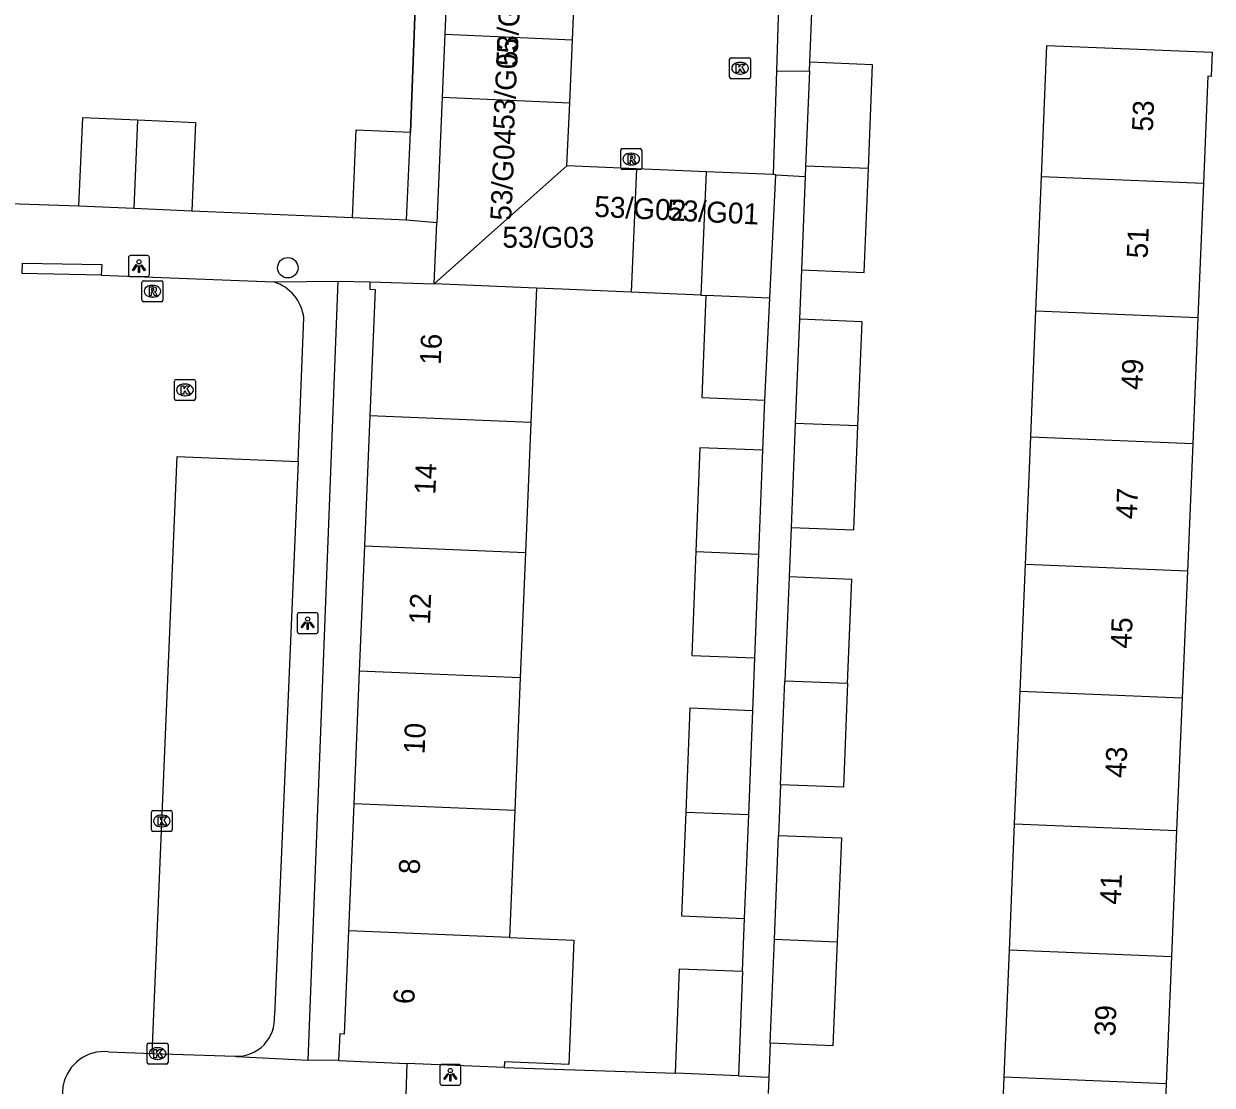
# Model space of a CAD drawing. Extents: x 161355 to 162026, y 386504 to 387459.
# Drawn here: x 161688.1 to 161744.9, y 387342.4 to 387393.1 of the extents above; entities that cross this region are included whole.
import ezdxf

# ---------------------------------------------------------------- set-up
doc = ezdxf.new("R2010")
doc.units = 0
for name, color, linetype in [('IMGEO_Boom', 7, 'Continuous'), ('IMGEO_Kolk', 7, 'Continuous'), ('IMGEO_Lichtpunt', 7, 'Continuous'), ('IMGEO_Muur', 7, 'Continuous'), ('IMGEO_Pand', 7, 'Continuous'), ('IMGEO_Pand_nummerreeks', 7, 'Continuous'), ('IMGEO_Rijbaan_lokaal_open', 7, 'Continuous'), ('IMGEO_Rioolput', 7, 'Continuous'), ('IMGEO_Voetpad_open', 7, 'Continuous')]:
    doc.layers.add(name, color=color, linetype=linetype)

msp = doc.modelspace()

# ---------------------------------------------------------------- linework, layer by layer
at = {"layer": 'IMGEO_Boom'}
msp.add_circle((161700.747, 387381.482), 0.489, dxfattribs=at)
at = {"layer": 'IMGEO_Kolk'}
for p, q in [((161721.849, 387390.588), (161721.849, 387391.44)), ((161721.924, 387391.514), (161722.776, 387391.514)), ((161722.337, 387391.294), (161722.362, 387391.294)), ((161722.85, 387391.44), (161722.85, 387390.588)), ((161722.776, 387390.514), (161721.924, 387390.514)), ((161722.36, 387390.734), (161722.335, 387390.734)), ((161695.335, 387375.22), (161695.335, 387376.072)), ((161695.41, 387376.146), (161696.262, 387376.146)), ((161695.823, 387375.926), (161695.848, 387375.926)), ((161696.336, 387376.072), (161696.336, 387375.22)), ((161696.262, 387375.146), (161695.41, 387375.146)), ((161695.846, 387375.366), (161695.821, 387375.366)), ((161694.231, 387354.628), (161694.231, 387355.48)), ((161694.306, 387355.554), (161695.158, 387355.554)), ((161694.719, 387355.334), (161694.744, 387355.334)), ((161695.232, 387355.48), (161695.232, 387354.628)), ((161694.742, 387354.774), (161694.717, 387354.774)), ((161695.158, 387354.554), (161694.306, 387354.554)), ((161694.029, 387343.517), (161694.029, 387344.369)), ((161694.104, 387344.443), (161694.956, 387344.443)), ((161694.517, 387344.223), (161694.542, 387344.223)), ((161695.03, 387344.369), (161695.03, 387343.517)), ((161694.956, 387343.443), (161694.104, 387343.443)), ((161694.54, 387343.663), (161694.515, 387343.663))]:
    msp.add_line(p, q, dxfattribs=at)
for points in [[(161721.849, 387390.588), (161721.849, 387391.44)], [(161721.924, 387391.514), (161722.776, 387391.514)], [(161722.17, 387391.214), (161722.293, 387391.214), (161722.293, 387391.063), (161722.423, 387391.214), (161722.587, 387391.214), (161722.441, 387391.063), (161722.594, 387390.814), (161722.442, 387390.814), (161722.357, 387390.978), (161722.293, 387390.911), (161722.293, 387390.814), (161722.17, 387390.814), (161722.17, 387391.214)], [(161722.85, 387391.44), (161722.85, 387390.588)], [(161722.776, 387390.514), (161721.924, 387390.514)], [(161695.335, 387375.22), (161695.335, 387376.072)], [(161695.41, 387376.146), (161696.262, 387376.146)], [(161695.656, 387375.846), (161695.779, 387375.846), (161695.779, 387375.695), (161695.909, 387375.846), (161696.073, 387375.846), (161695.927, 387375.695), (161696.08, 387375.446), (161695.928, 387375.446), (161695.843, 387375.61), (161695.779, 387375.543), (161695.779, 387375.446), (161695.656, 387375.446), (161695.656, 387375.846)], [(161696.336, 387376.072), (161696.336, 387375.22)], [(161696.262, 387375.146), (161695.41, 387375.146)], [(161694.231, 387354.628), (161694.231, 387355.48)], [(161694.306, 387355.554), (161695.158, 387355.554)], [(161695.232, 387355.48), (161695.232, 387354.628)], [(161694.552, 387355.254), (161694.675, 387355.254), (161694.675, 387355.103), (161694.805, 387355.254), (161694.969, 387355.254), (161694.823, 387355.103), (161694.976, 387354.854), (161694.824, 387354.854), (161694.739, 387355.018), (161694.675, 387354.951), (161694.675, 387354.854), (161694.552, 387354.854), (161694.552, 387355.254)], [(161695.158, 387354.554), (161694.306, 387354.554)], [(161694.029, 387343.517), (161694.029, 387344.369)], [(161694.104, 387344.443), (161694.956, 387344.443)], [(161694.35, 387344.143), (161694.473, 387344.143), (161694.473, 387343.992), (161694.603, 387344.143), (161694.767, 387344.143), (161694.621, 387343.992), (161694.774, 387343.743), (161694.622, 387343.743), (161694.537, 387343.907), (161694.473, 387343.84), (161694.473, 387343.743), (161694.35, 387343.743), (161694.35, 387344.143)], [(161695.03, 387344.369), (161695.03, 387343.517)], [(161694.956, 387343.443), (161694.104, 387343.443)]]:
    msp.add_lwpolyline(points, dxfattribs=at)
for centre, start, end in [((161721.926, 387391.438), 91.552, 178.448), ((161721.926, 387391.438), 91.552, 178.448), ((161722.774, 387391.438), 1.552, 88.448), ((161722.774, 387391.438), 1.552, 88.448), ((161721.926, 387390.59), 181.552, 268.448), ((161721.926, 387390.59), 181.552, 268.448), ((161722.774, 387390.59), 271.552, 358.448), ((161722.774, 387390.59), 271.552, 358.448), ((161695.412, 387376.07), 91.552, 178.448), ((161695.412, 387376.07), 91.552, 178.448), ((161696.26, 387376.07), 1.552, 88.448), ((161696.26, 387376.07), 1.552, 88.448), ((161695.412, 387375.222), 181.552, 268.448), ((161695.412, 387375.222), 181.552, 268.448), ((161696.26, 387375.222), 271.552, 358.448), ((161696.26, 387375.222), 271.552, 358.448), ((161694.308, 387355.478), 91.552, 178.448), ((161694.308, 387355.478), 91.552, 178.448), ((161695.156, 387355.478), 1.552, 88.448), ((161695.156, 387355.478), 1.552, 88.448), ((161694.308, 387354.63), 181.552, 268.448), ((161694.308, 387354.63), 181.552, 268.448), ((161695.156, 387354.63), 271.552, 358.448), ((161695.156, 387354.63), 271.552, 358.448), ((161694.106, 387344.367), 91.552, 178.448), ((161694.106, 387344.367), 91.552, 178.448), ((161694.954, 387344.367), 1.552, 88.448), ((161694.954, 387344.367), 1.552, 88.448), ((161694.106, 387343.519), 181.552, 268.448), ((161694.106, 387343.519), 181.552, 268.448), ((161694.954, 387343.519), 271.552, 358.448), ((161694.954, 387343.519), 271.552, 358.448)]:
    msp.add_arc(centre, 0.0765, start, end, dxfattribs=at)
for centre, major_axis, ratio, start_param, end_param in [((161722.336, 387391.014), (-0.387, 0.002), 0.722429, 4.712389, 7.853982), ((161722.361, 387391.014), (-0.39, 0.002), 0.717154, 1.570796, 4.712389), ((161695.822, 387375.646), (-0.387, 0.002), 0.722429, 4.712389, 7.853982), ((161695.847, 387375.646), (-0.39, 0.002), 0.717154, 1.570796, 4.712389), ((161694.718, 387355.054), (-0.387, 0.002), 0.722429, 4.712389, 7.853982), ((161694.743, 387355.054), (-0.39, 0.002), 0.717154, 1.570796, 4.712389), ((161694.516, 387343.943), (-0.387, 0.002), 0.722429, 4.712389, 7.853982), ((161694.541, 387343.943), (-0.39, 0.002), 0.717154, 1.570796, 4.712389)]:
    msp.add_ellipse(centre, major_axis=major_axis, ratio=ratio, start_param=start_param, end_param=end_param, dxfattribs=at)
at = {"layer": 'IMGEO_Lichtpunt'}
for p, q in [((161693.139, 387381.966), (161693.139, 387381.159)), ((161693.139, 387381.966), (161693.139, 387381.159)), ((161694.041, 387382.061), (161693.233, 387382.061)), ((161694.041, 387382.061), (161693.233, 387382.061)), ((161694.135, 387381.159), (161694.135, 387381.966)), ((161694.135, 387381.159), (161694.135, 387381.966)), ((161693.233, 387381.065), (161694.041, 387381.065)), ((161693.233, 387381.065), (161694.041, 387381.065)), ((161702.099, 387365.003), (161701.291, 387365.003)), ((161702.099, 387365.003), (161701.291, 387365.003)), ((161701.197, 387364.908), (161701.197, 387364.101)), ((161701.197, 387364.908), (161701.197, 387364.101)), ((161702.193, 387364.101), (161702.193, 387364.908)), ((161702.193, 387364.101), (161702.193, 387364.908)), ((161701.291, 387364.007), (161702.099, 387364.007)), ((161701.291, 387364.007), (161702.099, 387364.007)), ((161708.917, 387343.428), (161708.109, 387343.428)), ((161708.917, 387343.428), (161708.109, 387343.428)), ((161708.015, 387343.333), (161708.015, 387342.526)), ((161708.015, 387343.333), (161708.015, 387342.526)), ((161709.011, 387342.526), (161709.011, 387343.333)), ((161709.011, 387342.526), (161709.011, 387343.333)), ((161708.109, 387342.432), (161708.917, 387342.432)), ((161708.109, 387342.432), (161708.917, 387342.432))]:
    msp.add_line(p, q, dxfattribs=at)
for points in [[(161693.513, 387381.63), (161693.552, 387381.602), (161693.364, 387381.34), (161693.326, 387381.367), (161693.513, 387381.63)], [(161693.615, 387381.582), (161693.662, 387381.582), (161693.662, 387381.26), (161693.615, 387381.26), (161693.615, 387381.582)], [(161693.725, 387381.602), (161693.763, 387381.629), (161693.95, 387381.367), (161693.911, 387381.339), (161693.725, 387381.602)], [(161701.571, 387364.572), (161701.61, 387364.544), (161701.422, 387364.282), (161701.384, 387364.309), (161701.571, 387364.572)], [(161701.673, 387364.524), (161701.72, 387364.524), (161701.72, 387364.202), (161701.673, 387364.202), (161701.673, 387364.524)], [(161701.783, 387364.544), (161701.821, 387364.571), (161702.008, 387364.309), (161701.969, 387364.281), (161701.783, 387364.544)], [(161708.389, 387342.997), (161708.428, 387342.969), (161708.24, 387342.707), (161708.202, 387342.734), (161708.389, 387342.997)], [(161708.491, 387342.949), (161708.538, 387342.949), (161708.538, 387342.627), (161708.491, 387342.627), (161708.491, 387342.949)], [(161708.601, 387342.969), (161708.639, 387342.996), (161708.826, 387342.734), (161708.787, 387342.706), (161708.601, 387342.969)]]:
    msp.add_lwpolyline(points, dxfattribs=at)
for centre in [(161693.638, 387381.764), (161701.696, 387364.706), (161708.514, 387343.131)]:
    msp.add_circle(centre, 0.0994, dxfattribs=at)
for centre, start, end in [((161693.233, 387381.966), 90, 180), ((161693.233, 387381.966), 90, 180), ((161694.041, 387381.966), 0, 90), ((161694.041, 387381.966), 0, 90), ((161693.233, 387381.159), 180, 270), ((161693.233, 387381.159), 180, 270), ((161694.041, 387381.159), 270, 0), ((161694.041, 387381.159), 270, 360), ((161701.291, 387364.908), 90, 180), ((161701.291, 387364.908), 90, 180), ((161702.099, 387364.908), 0, 90), ((161702.099, 387364.908), 0, 90), ((161701.291, 387364.101), 180, 270), ((161701.291, 387364.101), 180, 270), ((161702.099, 387364.101), 270, 0), ((161702.099, 387364.101), 270, 360), ((161708.109, 387343.333), 90, 180), ((161708.109, 387343.333), 90, 180), ((161708.917, 387343.333), 0, 90), ((161708.917, 387343.333), 0, 90), ((161708.109, 387342.526), 180, 270), ((161708.109, 387342.526), 180, 270), ((161708.917, 387342.526), 270, 0), ((161708.917, 387342.526), 270, 360)]:
    msp.add_arc(centre, 0.0946, start, end, dxfattribs=at)
at = {"layer": 'IMGEO_Muur'}
msp.add_lwpolyline([(161706.839, 387393.897), (161706.606, 387387.966)], dxfattribs=at)
at = {"layer": 'IMGEO_Pand'}
for points in [[(161708.375, 387395.648), (161708.247, 387392.637)], [(161714.341, 387392.376), (161714.469, 387395.388)], [(161708.247, 387392.637), (161708.118, 387389.626)], [(161708.247, 387392.637), (161714.341, 387392.376)], [(161714.212, 387389.365), (161714.341, 387392.376)], [(161736.748, 387385.822), (161737.009, 387392.105), (161744.902, 387391.778), (161744.854, 387390.625), (161744.698, 387390.632), (161744.485, 387385.5)], [(161725.663, 387390.867), (161725.68, 387391.296)], [(161728.478, 387386.219), (161728.678, 387391.175), (161725.68, 387391.296)], [(161725.663, 387390.867), (161725.48, 387386.34)], [(161708.118, 387389.626), (161707.989, 387386.615), (161707.862, 387383.636)], [(161708.118, 387389.626), (161714.212, 387389.365)], [(161714.083, 387386.354), (161714.212, 387389.365)], [(161690.767, 387384.424), (161690.951, 387388.662), (161693.568, 387388.548)], [(161693.568, 387388.548), (161693.397, 387384.31)], [(161693.568, 387388.548), (161696.343, 387388.428), (161696.159, 387384.19)], [(161703.836, 387383.863), (161704.017, 387388.076), (161706.606, 387387.966)], [(161706.425, 387383.752), (161706.606, 387387.966)], [(161714.083, 387386.354), (161712.21, 387384.69), (161707.737, 387380.716)], [(161717.407, 387386.212), (161714.083, 387386.354)], [(161717.407, 387386.212), (161717.154, 387380.313)], [(161720.731, 387386.069), (161717.407, 387386.212)], [(161720.731, 387386.069), (161720.478, 387380.171)], [(161723.931, 387385.932), (161720.731, 387386.069)], [(161724.055, 387385.927), (161723.931, 387385.932)], [(161725.28, 387381.384), (161728.278, 387381.263), (161728.478, 387386.219)], [(161725.48, 387386.34), (161725.46, 387385.841)], [(161728.478, 387386.219), (161725.48, 387386.34)], [(161723.771, 387380.034), (161724.055, 387385.927)], [(161725.46, 387385.841), (161725.28, 387381.384)], [(161736.482, 387379.425), (161736.748, 387385.822)], [(161744.485, 387385.5), (161736.748, 387385.822)], [(161744.485, 387385.5), (161744.219, 387379.103)], [(161693.397, 387384.31), (161690.767, 387384.424)], [(161696.159, 387384.19), (161693.397, 387384.31)], [(161706.425, 387383.752), (161703.836, 387383.863)], [(161707.737, 387380.716), (161707.862, 387383.636)], [(161704.673, 387380.804), (161704.659, 387380.46), (161704.919, 387380.449), (161704.669, 387374.41)], [(161704.673, 387380.804), (161707.737, 387380.716)], [(161712.624, 387380.507), (161707.737, 387380.716)], [(161712.624, 387380.507), (161712.359, 387374.091)], [(161717.154, 387380.313), (161713.831, 387380.455), (161712.624, 387380.507)], [(161720.478, 387380.171), (161717.154, 387380.313)], [(161720.478, 387380.171), (161720.719, 387380.161)], [(161720.719, 387380.161), (161720.528, 387375.28), (161723.536, 387375.162)], [(161723.771, 387380.034), (161720.719, 387380.161)], [(161723.536, 387375.162), (161723.771, 387380.034)], [(161736.232, 387373.404), (161736.482, 387379.425)], [(161736.482, 387379.425), (161744.219, 387379.103)], [(161725.185, 387379.02), (161724.984, 387374.045)], [(161727.981, 387373.924), (161728.182, 387378.899), (161725.185, 387379.02)], [(161744.219, 387379.103), (161743.969, 387373.082)], [(161704.669, 387374.41), (161704.412, 387368.205)], [(161712.359, 387374.091), (161704.669, 387374.41)], [(161712.359, 387374.091), (161712.102, 387367.886)], [(161724.984, 387374.045), (161724.783, 387369.079)], [(161727.981, 387373.924), (161724.984, 387374.045)], [(161724.783, 387369.079), (161727.781, 387368.958), (161727.981, 387373.924)], [(161723.442, 387372.763), (161720.434, 387372.881), (161720.24, 387367.925)], [(161735.979, 387367.31), (161736.232, 387373.404)], [(161736.232, 387373.404), (161743.969, 387373.082)], [(161743.969, 387373.082), (161743.716, 387366.988)], [(161723.248, 387367.807), (161723.442, 387372.763)], [(161704.412, 387368.205), (161704.164, 387362.214)], [(161704.412, 387368.205), (161712.102, 387367.886)], [(161712.102, 387367.886), (161711.854, 387361.895)], [(161720.24, 387367.925), (161720.046, 387362.962), (161723.054, 387362.845)], [(161720.24, 387367.925), (161723.248, 387367.807)], [(161723.054, 387362.845), (161723.248, 387367.807)], [(161735.728, 387361.261), (161735.979, 387367.31)], [(161743.716, 387366.988), (161735.979, 387367.31)], [(161724.688, 387366.713), (161724.487, 387361.751)], [(161727.485, 387361.63), (161727.685, 387366.592), (161724.688, 387366.713)], [(161743.716, 387366.988), (161743.465, 387360.939)], [(161704.164, 387362.214), (161703.902, 387355.879)], [(161711.854, 387361.895), (161704.164, 387362.214)], [(161711.854, 387361.895), (161711.592, 387355.56)], [(161724.287, 387356.786), (161724.487, 387361.751)], [(161727.485, 387361.63), (161727.284, 387356.664), (161724.287, 387356.786)], [(161724.487, 387361.751), (161727.485, 387361.63)], [(161735.465, 387354.918), (161735.728, 387361.261)], [(161735.728, 387361.261), (161743.465, 387360.939)], [(161722.955, 387360.321), (161719.947, 387360.438), (161719.754, 387355.482)], [(161743.465, 387360.939), (161743.201, 387354.596)], [(161722.761, 387355.365), (161722.955, 387360.321)], [(161703.902, 387355.879), (161703.65, 387349.806)], [(161711.592, 387355.56), (161703.902, 387355.879)], [(161711.592, 387355.56), (161711.341, 387349.487)], [(161719.754, 387355.482), (161719.559, 387350.521), (161722.567, 387350.403)], [(161719.754, 387355.482), (161722.761, 387355.365)], [(161722.567, 387350.403), (161722.761, 387355.365)], [(161735.214, 387348.884), (161735.465, 387354.918)], [(161735.465, 387354.918), (161743.201, 387354.596)], [(161723.989, 387349.406), (161724.189, 387354.367)], [(161724.189, 387354.367), (161727.187, 387354.246), (161726.986, 387349.285)], [(161743.201, 387354.596), (161742.951, 387348.562)], [(161703.65, 387349.806), (161703.446, 387344.875), (161703.229, 387344.884), (161703.176, 387343.61)], [(161711.341, 387349.487), (161703.65, 387349.806)], [(161711.341, 387349.487), (161714.41, 387349.36), (161714.164, 387343.427), (161711.095, 387343.554), (161711.084, 387343.283)], [(161723.788, 387344.44), (161723.989, 387349.406)], [(161726.986, 387349.285), (161726.786, 387344.319), (161723.788, 387344.44)], [(161723.989, 387349.406), (161726.986, 387349.285)], [(161734.962, 387342.813), (161735.214, 387348.884)], [(161742.951, 387348.562), (161735.214, 387348.884)], [(161742.951, 387348.562), (161742.698, 387342.491)], [(161719.265, 387343.003), (161719.46, 387347.99), (161722.468, 387347.872)], [(161722.468, 387347.872), (161722.273, 387342.873)], [(161703.176, 387343.61), (161706.431, 387343.475)], [(161711.084, 387343.283), (161706.431, 387343.475)], [(161722.273, 387342.873), (161719.265, 387343.003)], [(161734.705, 387336.64), (161734.962, 387342.813)], [(161742.698, 387342.491), (161734.962, 387342.813)], [(161742.698, 387342.491), (161742.442, 387336.318)]]:
    msp.add_lwpolyline(points, dxfattribs=at)
at = {"layer": 'IMGEO_Rijbaan_lokaal_open'}
for points in [[(161724.178, 387393.997), (161724.083, 387390.891)], [(161724.083, 387390.891), (161723.931, 387385.932)], [(161691.84, 387381.135), (161688.053, 387381.209)], [(161691.84, 387381.135), (161700.085, 387380.803)], [(161701.237, 387372.219), (161701.514, 387379.085)], [(161694.268, 387343.953), (161695.456, 387372.46), (161701.237, 387372.219)], [(161692.182, 387344.022), (161694.268, 387343.953)], [(161688.221, 387295.718), (161688.277, 387296.793), (161688.52, 387305.232), (161690.025, 387342.43)]]:
    msp.add_lwpolyline(points, dxfattribs=at)
for centre, radius, start, end in [((161699.482, 387378.848), 2.046, 6.6584, 72.8477), ((161691.96, 387342.066), 1.969, 83.5268, 169.3324)]:
    msp.add_arc(centre, radius, start, end, dxfattribs=at)
at = {"layer": 'IMGEO_Rioolput'}
for p, q in [((161716.65, 387386.248), (161716.65, 387387.1)), ((161716.725, 387387.174), (161717.577, 387387.174)), ((161717.651, 387387.1), (161717.651, 387386.248)), ((161717.138, 387386.954), (161717.163, 387386.954)), ((161717.577, 387386.174), (161716.725, 387386.174)), ((161717.161, 387386.394), (161717.136, 387386.394)), ((161693.859, 387380.86), (161694.711, 387380.86)), ((161693.784, 387379.934), (161693.784, 387380.786)), ((161694.272, 387380.64), (161694.297, 387380.64)), ((161694.785, 387380.786), (161694.785, 387379.934)), ((161694.711, 387379.86), (161693.859, 387379.86)), ((161694.295, 387380.08), (161694.27, 387380.08))]:
    msp.add_line(p, q, dxfattribs=at)
for points in [[(161716.65, 387386.248), (161716.65, 387387.1)], [(161716.725, 387387.174), (161717.577, 387387.174)], [(161717.651, 387387.1), (161717.651, 387386.248)], [(161717.239, 387386.872), (161716.987, 387386.874), (161716.987, 387386.474)], [(161716.987, 387386.474), (161717.111, 387386.474), (161717.111, 387386.636), (161717.122, 387386.636)], [(161717.165, 387386.793), (161717.111, 387386.793), (161717.111, 387386.712)], [(161717.111, 387386.712), (161717.163, 387386.712)], [(161717.169, 387386.607), (161717.24, 387386.474), (161717.38, 387386.474), (161717.315, 387386.6)], [(161717.577, 387386.174), (161716.725, 387386.174)], [(161693.859, 387380.86), (161694.711, 387380.86)], [(161693.784, 387379.934), (161693.784, 387380.786)], [(161694.373, 387380.558), (161694.121, 387380.56), (161694.121, 387380.16)], [(161694.121, 387380.16), (161694.245, 387380.16), (161694.245, 387380.322), (161694.256, 387380.322)], [(161694.299, 387380.479), (161694.245, 387380.479), (161694.245, 387380.398)], [(161694.245, 387380.398), (161694.297, 387380.398)], [(161694.303, 387380.293), (161694.374, 387380.16), (161694.514, 387380.16), (161694.449, 387380.286)], [(161694.785, 387380.786), (161694.785, 387379.934)], [(161694.711, 387379.86), (161693.859, 387379.86)]]:
    msp.add_lwpolyline(points, dxfattribs=at)
for centre, radius, start, end in [((161716.727, 387387.098), 0.0765, 91.552, 178.448), ((161716.727, 387387.098), 0.0765, 91.552, 178.448), ((161717.575, 387387.098), 0.0765, 1.552, 88.448), ((161717.575, 387387.098), 0.0765, 1.552, 88.448), ((161717.121, 387386.583), 0.0533, 26.0293, 88.6989), ((161717.147, 387386.901), 0.19, 274.7715, 282.9687), ((161717.171, 387386.697), 0.0964, 77.0061, 93.1865), ((161717.185, 387386.754), 0.0378, 276.6634, 79.6772), ((161717.238, 387386.762), 0.109, 350.3612, 89.416), ((161717.236, 387386.762), 0.112, 277.5842, 350.9817), ((161717.22, 387386.547), 0.108, 29.5134, 73.7905), ((161716.727, 387386.25), 0.0765, 181.552, 268.448), ((161716.727, 387386.25), 0.0765, 181.552, 268.448), ((161717.575, 387386.25), 0.0765, 271.552, 358.448), ((161717.575, 387386.25), 0.0765, 271.552, 358.448), ((161693.861, 387380.784), 0.0765, 91.552, 178.448), ((161693.861, 387380.784), 0.0765, 91.552, 178.448), ((161694.709, 387380.784), 0.0765, 1.552, 88.448), ((161694.709, 387380.784), 0.0765, 1.552, 88.448), ((161694.255, 387380.269), 0.0533, 26.0293, 88.6989), ((161694.281, 387380.587), 0.19, 274.7715, 282.9687), ((161694.305, 387380.383), 0.0964, 77.0061, 93.1865), ((161694.319, 387380.44), 0.0378, 276.6634, 79.6772), ((161694.372, 387380.448), 0.109, 350.3612, 89.416), ((161694.37, 387380.448), 0.112, 277.5842, 350.9817), ((161694.354, 387380.233), 0.108, 29.5134, 73.7905), ((161693.861, 387379.936), 0.0765, 181.552, 268.448), ((161693.861, 387379.936), 0.0765, 181.552, 268.448), ((161694.709, 387379.936), 0.0765, 271.552, 358.448), ((161694.709, 387379.936), 0.0765, 271.552, 358.448)]:
    msp.add_arc(centre, radius, start, end, dxfattribs=at)
for centre, major_axis, ratio, start_param, end_param in [((161717.137, 387386.674), (-0.387, 0.002), 0.722429, 4.712389, 7.853982), ((161717.162, 387386.674), (-0.39, 0.002), 0.717154, 1.570796, 4.712389), ((161694.271, 387380.36), (-0.387, 0.002), 0.722429, 4.712389, 7.853982), ((161694.296, 387380.36), (-0.39, 0.002), 0.717154, 1.570796, 4.712389)]:
    msp.add_ellipse(centre, major_axis=major_axis, ratio=ratio, start_param=start_param, end_param=end_param, dxfattribs=at)
at = {"layer": 'IMGEO_Voetpad_open'}
for points in [[(161725.68, 387391.296), (161725.808, 387394.467)], [(161706.606, 387387.966), (161706.839, 387393.897)], [(161724.083, 387390.891), (161725.663, 387390.867)], [(161724.055, 387385.927), (161725.46, 387385.841)], [(161690.767, 387384.424), (161687.439, 387384.537), (161683.287, 387384.678)], [(161703.836, 387383.863), (161696.159, 387384.19)], [(161707.862, 387383.636), (161706.425, 387383.752)], [(161688.053, 387381.209), (161688.073, 387381.708), (161691.86, 387381.634), (161691.84, 387381.135)], [(161700.085, 387380.803), (161703.159, 387380.841)], [(161701.728, 387343.63), (161703.159, 387380.841)], [(161703.159, 387380.841), (161704.673, 387380.804)], [(161725.28, 387381.384), (161725.185, 387379.02)], [(161723.442, 387372.763), (161723.536, 387375.162)], [(161701.237, 387372.219), (161700.113, 387345.76)], [(161724.783, 387369.079), (161724.688, 387366.713)], [(161722.955, 387360.321), (161723.054, 387362.845)], [(161724.287, 387356.786), (161724.189, 387354.367)], [(161722.468, 387347.872), (161722.567, 387350.403)], [(161694.268, 387343.953), (161698.237, 387343.817)], [(161723.788, 387344.44), (161723.722, 387342.811)], [(161698.237, 387343.817), (161698.297, 387343.807), (161701.728, 387343.63)], [(161703.176, 387343.61), (161701.728, 387343.63)], [(161706.431, 387343.475), (161706.356, 387340.963)], [(161711.084, 387343.283), (161719.265, 387343.003)], [(161722.273, 387342.873), (161723.722, 387342.811)], [(161723.722, 387342.811), (161723.691, 387342.043)]]:
    msp.add_lwpolyline(points, dxfattribs=at)
msp.add_arc((161698.313, 387345.62), 1.805, 267.572, 4.4382, dxfattribs=at)

# ---------------------------------------------------------------- texts
at = {"layer": 'IMGEO_Pand_nummerreeks'}
for s, rotation, p in [('53/G06', 87.3012, (161711.697, 387391.092)), ('53/G05', 87.3012, (161711.556, 387388.056)), ('53', 87.6216, (161742.065, 387387.976)), ('53/G04', 87.3012, (161711.415, 387383.714)), ('53/G02', 357.3012, (161715.372, 387383.919)), ('53/G01', 357.3014, (161718.851, 387383.75)), ('53/G03', 0, (161710.999, 387382.439)), ('51', 87.6216, (161741.814, 387381.914)), ('16', 87.6289, (161708.052, 387376.827)), ('49', 87.6216, (161741.552, 387375.627)), ('14', 87.6289, (161707.795, 387370.628)), ('47', 87.6216, (161741.296, 387369.452)), ('12', 87.6289, (161707.538, 387364.425)), ('45', 87.6216, (161741.039, 387363.277)), ('10', 87.6289, (161707.281, 387358.232)), ('43', 87.6216, (161740.783, 387357.102)), ('8', 87.6289, (161707.044, 387352.494)), ('41', 87.6216, (161740.531, 387351.04)), ('6', 87.6282, (161706.787, 387346.29)), ('39', 87.6216, (161740.27, 387344.752))]:
    msp.add_text(s, height=1, rotation=rotation, dxfattribs=at).set_placement(p)

doc.saveas('drawing.dxf')
